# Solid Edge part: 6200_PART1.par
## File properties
Author: PARTuser1
Template: Normal.par
Last saved by: Francesco
Revision: 3
Application: Solid Edge
Material: Acciaio
Stile della faccia: Acciaio
Stile di riempimento: ANSI32(Acciaio)
Stile virtuale: Acciaio lavorato a macchina
Coef. of Thermal Exp: 0.0
Thermal Conductivity: 32.0
Specific Heat: 481.0
Modulus of Elasticity: 199947953000.0
Poisson's Ratio: 0.29
Yield Stress: 262000766.0
Ultimate Stress: 358527364.0
Elongation: 0.0
Tipo di contenuto documento: 0
Density: 7833,000 kg/m^3
Accuracy: 0,990
CADENASNORM: 6200_PART1
CADENAS_NB: 6200_PART1
CADENAS_NN: _PART1
CADENAS_NBSYN: 6200_PART1
CADENAS_LINA: 6200_PART1
CADENAS_Z: 8.000
CADENAS_Y0W2: 9.239
CADENAS_R0N1: 0.000
CADENAS_DOUT: 30.000
CADENAS_YI: 8.500
CADENAS_D1ICOS: 23.200
CADENAS_YE: 11.600
CADENAS_Y0I: 10.000
CADENAS_D2: 24.800
CADENAS_D1: 23.200
CADENAS_Y0E: 10.000
CADENAS_X0I: 4.500
CADENAS_BN1: 0.000
CADENAS_CE: 0.000
CADENAS_R2I: 0.200
CADENAS_RWB: 2.381
CADENAS_X0E: 4.500
CADENAS_R2E: 0.200
CADENAS_Z0W2: 3.827
CADENAS_RI: 2.381
CADENAS_X0WB: 4.500
CADENAS_BICOS: 0.000
CADENAS_HIS1: 0.000
CADENAS_RE: 2.381
CADENAS_XI: 0.000
CADENAS_RC: 0.000
CADENAS_XE: 0.000
CADENAS_HE2: 2.600
CADENAS_X0W2: 4.500
CADENAS_BOREDIAMETER: 10.000
CADENAS_RSG: 0.283
CADENAS_BI: 9.000
CADENAS_HN1: 0.000
CADENAS_HI: 3.500
CADENAS_BE: 9.000
CADENAS_R1I: 0.600
CADENAS_HH: 0.000
CADENAS_PRODUCTID: 1050010200.000
CADENAS_HE: 3.400
CADENAS_BEARINGWIDTH: 9.000
CADENAS_R1E: 0.600
CADENAS_BICOS1: 0.000
CADENAS_HICOS: 0.000
CADENAS_DKI: 17.000
CADENAS_Y0WB: 10.000
CADENAS_comment: design:dgbb1; version:5000.3; lang:it; selectedUnitParts:000000; action:download; skf2d3daction.jsp version:2008-03-06; getRequestURI:/skf/skf3dnew/skf2d3daction.jsp
CADENAS_KT: DUMMY
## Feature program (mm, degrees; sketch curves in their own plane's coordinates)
sketch for "unnamed RevolvedProtrusion 1" plane through (0, 0, 0) normal (0, 0, 1) x-axis (1, 0, 0)
  arc centre (0.6, 5.6) radius 0.6 from (0, 5.6) to (0.6, 5) ccw
  line (0.6, 5) -> (8.4, 5)
  arc centre (8.4, 5.6) radius 0.6 from (8.4, 5) to (9, 5.6) ccw
  line (9, 5.6) -> (9, 8.3)
  arc centre (8.8, 8.3) radius 0.2 from (9, 8.3) to (8.8, 8.5) ccw
  line (8.8, 8.5) -> (6.3491, 8.5)
  arc centre (4.5, 10) radius 2.381 from (6.3491, 8.5) to (2.6509, 8.5) cw
  line (2.6509, 8.5) -> (0.2, 8.5)
  arc centre (0.2, 8.3) radius 0.2 from (0.2, 8.5) to (0, 8.3) ccw
  line (0, 8.3) -> (0, 5.6)
revolve "unnamed RevolvedProtrusion 1" add finite 360 deg about sketch line (8.4, 0) -> (0.6, 0)
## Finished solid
Body 1: solid body, 10 faces, 10 edges, 0 vertices.
  Faces by surface: torus 5, cylinder 3, plane 2
  Edges by curve: circle 10
Bounding box of the edges (mm; curved faces can reach further): 9.000 x 17.000 x 17.000, from (0, -8.5, -8.5) to (9, 8.5, 8.5).
Cylindrical faces by radius (mm): R5 x1, R8.5 x2
Toroidal faces (ring radius, tube radius in mm): R5.6 r0.6 x2, R8.3 r0.2 x2, R10 r2.381 x1
Planar faces by outward normal: +x 1, -x 1
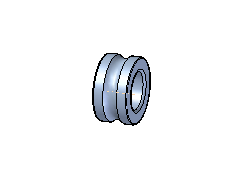
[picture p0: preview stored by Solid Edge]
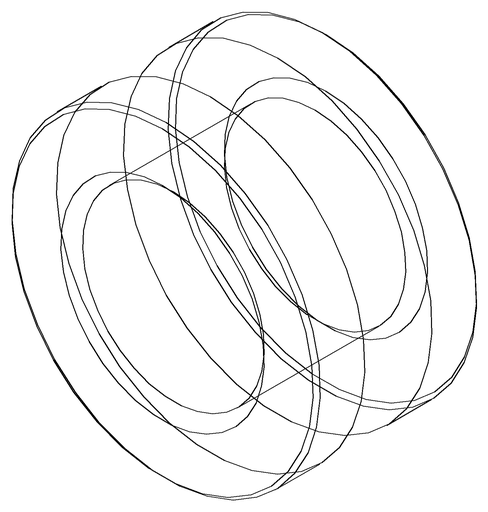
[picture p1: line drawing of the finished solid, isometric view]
